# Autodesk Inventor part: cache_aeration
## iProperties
Created: 2011-01
Part Number: cache_aeration
Document SubType Name: Modeling
Designer: eric
Density: 1 g/cm^3
Mass: 1.81962 g
Surface Area: 74.1775 cm^2
Volume: 1.81962 cm^3
Author: eric
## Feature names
1. Base1
